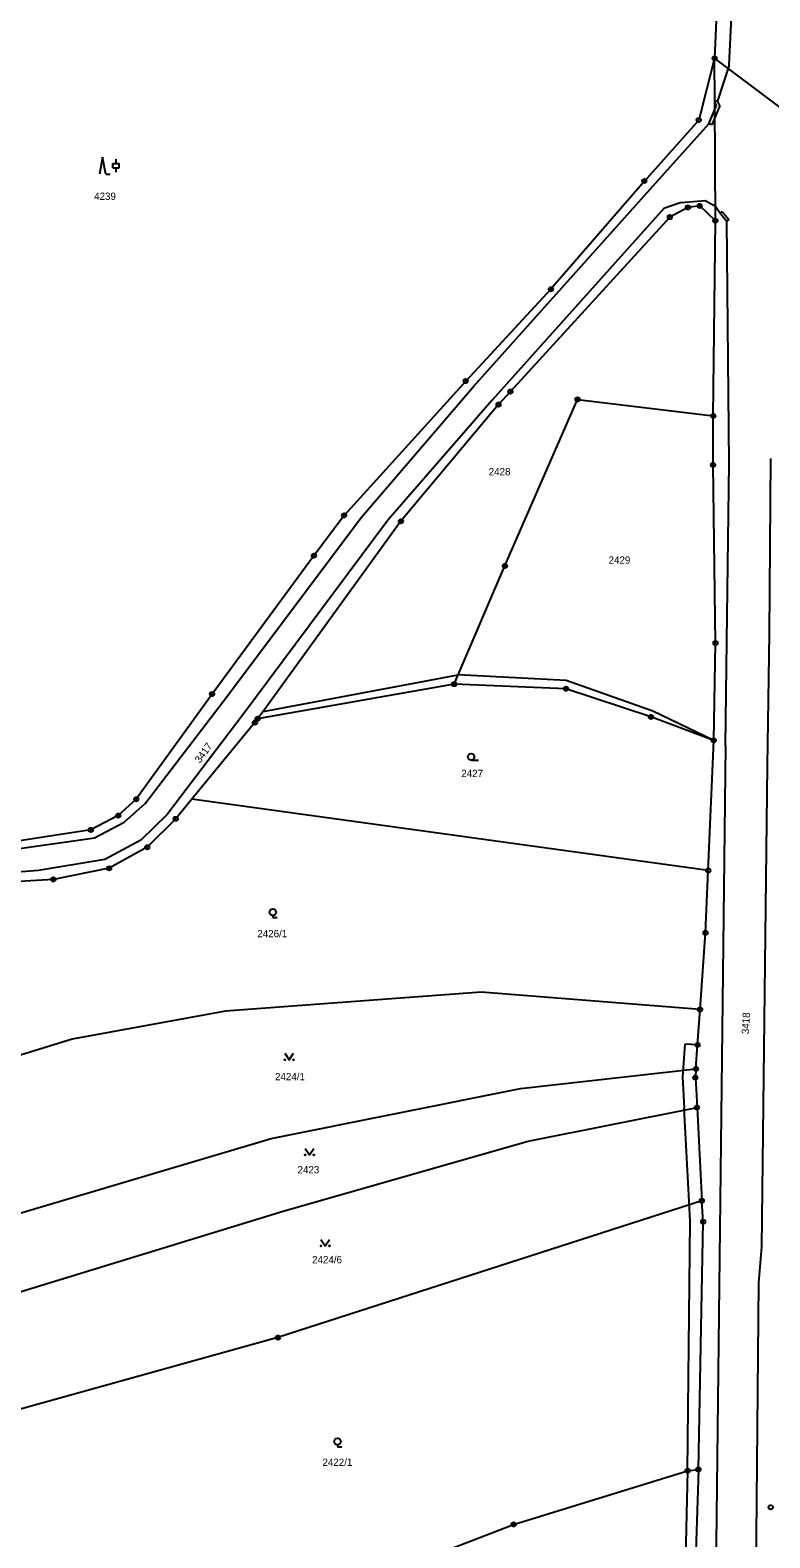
# Model space of a CAD drawing. Extents: x -733394 to -722299, y -1082822 to -1075049.
# Drawn here: x -729552.1 to -729380.2, y -1080085.2 to -1079734.5 of the extents above; entities that cross this region are included whole.
import ezdxf

# ---------------------------------------------------------------- set-up
doc = ezdxf.new("R2010")
doc.units = 0
for name, color, linetype in [('Hranice parcel', 7, 'Continuous'), ('Parcelní čísla', 7, 'Continuous'), ('Vnitřní kresba', 7, 'Continuous'), ('Značky bodu BP', 7, 'Continuous'), ('Značky kultur', 7, 'Continuous')]:
    doc.layers.add(name, color=color, linetype=linetype)

msp = doc.modelspace()

# ---------------------------------------------------------------- linework, layer by layer
at = {"layer": 'Hranice parcel'}
for p, q in [((-729375.36, -1079754.23), (-729393, -1079741.04)), ((-729393.31, -1079824.23), (-729392.83, -1079778.82)), ((-729453.54, -1079886.63), (-729499.23, -1079894.69)), ((-729394.5, -1079929.98), (-729393.2, -1079899.71)), ((-729394.5, -1079929.98), (-729514.52, -1079913.4)), ((-729397.1, -1079985.13), (-729395.98, -1080006.81)), ((-729399.29, -1080069.6), (-729400.21, -1080106.83))]:
    msp.add_line(p, q, dxfattribs=at)
for points in [[(-729389.9, -1079596.94), (-729389.91, -1079599.78), (-729391.17, -1079698.92), (-729393, -1079741.04)], [(-729393, -1079741.04), (-729396.69, -1079755.42), (-729409.34, -1079769.58), (-729431.05, -1079794.75), (-729450.87, -1079816.13), (-729479.14, -1079847.37), (-729486.14, -1079856.74), (-729509.81, -1079888.93), (-729527.42, -1079913.39), (-729531.62, -1079917.21), (-729537.99, -1079920.53), (-729560.17, -1079923.94), (-729604.91, -1079926.77), (-729628.92, -1079931.64), (-729650.34, -1079939.02)], [(-729392.83, -1079778.82), (-729392.95, -1079751.19), (-729393, -1079741.04)], [(-729392.83, -1079778.82), (-729396.48, -1079775.37), (-729399.23, -1079775.72), (-729403.42, -1079777.97), (-729440.47, -1079818.56), (-729443.24, -1079821.6), (-729465.91, -1079848.75), (-729497.97, -1079892.96), (-729499.23, -1079894.69)], [(-729453.54, -1079886.63), (-729452.59, -1079884.43), (-729441.74, -1079859.13), (-729424.88, -1079820.38), (-729393.31, -1079824.23)], [(-729393.2, -1079899.71), (-729392.8, -1079877.07), (-729393.37, -1079835.62), (-729393.31, -1079824.23)], [(-729393.2, -1079899.71), (-729407.8, -1079894.26), (-729427.58, -1079887.71), (-729453.54, -1079886.63)], [(-729499.23, -1079894.69), (-729499.86, -1079895.58), (-729514.52, -1079913.4)], [(-729514.52, -1079913.4), (-729518.27, -1079917.96), (-729524.89, -1079924.56), (-729533.73, -1079929.47), (-729546.69, -1079932.06), (-729554.56, -1079932.52)], [(-729396.38, -1079962.31), (-729395.13, -1079944.49), (-729394.5, -1079929.98)], [(-729396.38, -1079962.31), (-729447.28, -1079958.27), (-729506.69, -1079962.69), (-729542.32, -1079969.19), (-729585.71, -1079982.62)], [(-729397.35, -1079976.13), (-729396.96, -1079970.56), (-729396.38, -1079962.31)], [(-729572.38, -1080014.98), (-729571.76, -1080014.77), (-729496.1, -1079992.29), (-729438.14, -1079980.7), (-729397.35, -1079976.13)], [(-729397.35, -1079976.13), (-729397.49, -1079978.16), (-729397.1, -1079985.13)], [(-729565.64, -1080031.37), (-729493.03, -1080009.17), (-729436.31, -1079992.96), (-729397.1, -1079985.13)], [(-729395.98, -1080006.81), (-729494.49, -1080038.62), (-729562.8, -1080057.65)], [(-729399.29, -1080069.6), (-729396.78, -1080069.32), (-729395.67, -1080011.7), (-729395.98, -1080006.81)], [(-729539.17, -1080119.69), (-729518.46, -1080112.52), (-729439.72, -1080082.09), (-729399.29, -1080069.6)]]:
    msp.add_lwpolyline(points, dxfattribs=at)
at = {"layer": 'Vnitřní kresba'}
for p, q in [((-729389.59, -1079742.64), (-729387.65, -1079698.9)), ((-729389.59, -1079742.64), (-729392.31, -1079750.91)), ((-729394.32, -1079756.27), (-729392.58, -1079752.05)), ((-729391.8, -1079752), (-729393.67, -1079756.54)), ((-729392.31, -1079750.91), (-729392.95, -1079751.19)), ((-729392.58, -1079752.05), (-729392.95, -1079751.19)), ((-729391.8, -1079752), (-729392.31, -1079750.91)), ((-729408.02, -1079771.46), (-729394.32, -1079756.27)), ((-729393.67, -1079756.54), (-729394.32, -1079756.27)), ((-729449.08, -1079817.41), (-729408.02, -1079771.46)), ((-729400.8, -1079774.55), (-729404.85, -1079775.95)), ((-729400.8, -1079774.55), (-729395.2, -1079774.11)), ((-729395.2, -1079774.11), (-729392.83, -1079775.42)), ((-729404.85, -1079775.95), (-729444.69, -1079820.56)), ((-729392.83, -1079775.42), (-729391.71, -1079777.03)), ((-729391.71, -1079777.03), (-729391.28, -1079776.67)), ((-729391.71, -1079777.03), (-729390.13, -1079778.92)), ((-729391.28, -1079776.67), (-729389.7, -1079778.56)), ((-729389.7, -1079778.56), (-729390.13, -1079778.92)), ((-729389.64, -1079835.21), (-729390.13, -1079778.92)), ((-729475.05, -1079847.8), (-729449.08, -1079817.41)), ((-729444.69, -1079820.56), (-729468.86, -1079848.44)), ((-729380.24, -1079874.92), (-729379.95, -1079834.13)), ((-729390.13, -1079876.61), (-729389.64, -1079835.21)), ((-729507.22, -1079890.66), (-729475.05, -1079847.8)), ((-729468.86, -1079848.44), (-729502.63, -1079893.73)), ((-729390.46, -1079900.98), (-729390.13, -1079876.61)), ((-729380.7, -1079905.52), (-729380.24, -1079874.92)), ((-729497.97, -1079892.96), (-729452.59, -1079884.43)), ((-729427.5, -1079885.77), (-729452.59, -1079884.43)), ((-729407.35, -1079892.89), (-729427.5, -1079885.77)), ((-729525.36, -1079914.42), (-729507.22, -1079890.66)), ((-729502.63, -1079893.73), (-729520.23, -1079916.98)), ((-729393.2, -1079899.71), (-729407.35, -1079892.89)), ((-729390.46, -1079900.98), (-729391.76, -1080013.37)), ((-729382.05, -1080017.51), (-729380.7, -1079905.52)), ((-729530.22, -1079918.74), (-729525.36, -1079914.42)), ((-729537.12, -1079922.35), (-729530.22, -1079918.74)), ((-729520.23, -1079916.98), (-729526.37, -1079922.94)), ((-729557.85, -1079925.34), (-729537.12, -1079922.35)), ((-729526.37, -1079922.94), (-729534.72, -1079927.4)), ((-729534.72, -1079927.4), (-729550.12, -1079929.99)), ((-729550.12, -1079929.99), (-729597.35, -1079933.72)), ((-729399.95, -1079970.37), (-729400.48, -1079977.95)), ((-729396.96, -1079970.56), (-729399.95, -1079970.37)), ((-729400.48, -1079977.95), (-729400.1, -1079985.3)), ((-729398.94, -1080007), (-729400.1, -1079985.3)), ((-729398.67, -1080011.64), (-729398.94, -1080007)), ((-729399.29, -1080069.6), (-729398.67, -1080011.64)), ((-729391.76, -1080013.37), (-729393.66, -1080168.69)), ((-729382.71, -1080025.88), (-729382.05, -1080017.51)), ((-729384.02, -1080169.17), (-729382.71, -1080025.88)), ((-729396.78, -1080069.32), (-729397.91, -1080106.9))]:
    msp.add_line(p, q, dxfattribs=at)
at = {"layer": 'Značky bodu BP'}
for centre, radius in [((-729393, -1079741.04), 0.5), ((-729393, -1079741.04), 0.0303), ((-729396.69, -1079755.42), 0.5), ((-729396.69, -1079755.42), 0.0303), ((-729409.34, -1079769.58), 0.5), ((-729409.34, -1079769.58), 0.0303), ((-729396.48, -1079775.37), 0.5), ((-729403.42, -1079777.97), 0.5), ((-729403.42, -1079777.97), 0.0303), ((-729399.23, -1079775.72), 0.5), ((-729399.23, -1079775.72), 0.0303), ((-729396.48, -1079775.37), 0.0303), ((-729392.83, -1079778.82), 0.5), ((-729392.83, -1079778.82), 0.0303), ((-729431.05, -1079794.75), 0.5), ((-729431.05, -1079794.75), 0.0303), ((-729450.87, -1079816.13), 0.5), ((-729450.87, -1079816.13), 0.0303), ((-729440.47, -1079818.56), 0.5), ((-729440.47, -1079818.56), 0.0303), ((-729424.88, -1079820.38), 0.5), ((-729424.88, -1079820.38), 0.0303), ((-729443.24, -1079821.6), 0.5), ((-729443.24, -1079821.6), 0.0303), ((-729393.31, -1079824.23), 0.5), ((-729393.31, -1079824.23), 0.0303), ((-729393.37, -1079835.62), 0.5), ((-729393.37, -1079835.62), 0.0303), ((-729479.14, -1079847.37), 0.5), ((-729479.14, -1079847.37), 0.0303), ((-729465.91, -1079848.75), 0.5), ((-729465.91, -1079848.75), 0.0303), ((-729486.14, -1079856.74), 0.5), ((-729486.14, -1079856.74), 0.0303), ((-729441.74, -1079859.13), 0.5), ((-729441.74, -1079859.13), 0.0303), ((-729392.8, -1079877.07), 0.5), ((-729392.8, -1079877.07), 0.0303), ((-729453.54, -1079886.63), 0.5), ((-729453.54, -1079886.63), 0.0303), ((-729427.58, -1079887.71), 0.5), ((-729509.81, -1079888.93), 0.5), ((-729509.81, -1079888.93), 0.0303), ((-729427.58, -1079887.71), 0.0303), ((-729499.23, -1079894.69), 0.5), ((-729407.8, -1079894.26), 0.5), ((-729407.8, -1079894.26), 0.0303), ((-729499.86, -1079895.58), 0.5), ((-729499.86, -1079895.58), 0.0303), ((-729499.23, -1079894.69), 0.0303), ((-729393.2, -1079899.71), 0.5), ((-729393.2, -1079899.71), 0.0303), ((-729527.42, -1079913.39), 0.5), ((-729527.42, -1079913.39), 0.0303), ((-729531.62, -1079917.21), 0.5), ((-729531.62, -1079917.21), 0.0303), ((-729518.27, -1079917.96), 0.5), ((-729518.27, -1079917.96), 0.0303), ((-729537.99, -1079920.53), 0.5), ((-729537.99, -1079920.53), 0.0303), ((-729524.89, -1079924.56), 0.5), ((-729524.89, -1079924.56), 0.0303), ((-729533.73, -1079929.47), 0.5), ((-729546.69, -1079932.06), 0.5), ((-729546.69, -1079932.06), 0.0303), ((-729533.73, -1079929.47), 0.0303), ((-729394.5, -1079929.98), 0.5), ((-729394.5, -1079929.98), 0.0303), ((-729395.13, -1079944.49), 0.5), ((-729395.13, -1079944.49), 0.0303), ((-729396.38, -1079962.31), 0.5), ((-729396.38, -1079962.31), 0.0303), ((-729396.96, -1079970.56), 0.5), ((-729396.96, -1079970.56), 0.0303), ((-729397.49, -1079978.16), 0.5), ((-729397.35, -1079976.13), 0.5), ((-729397.49, -1079978.16), 0.0303), ((-729397.35, -1079976.13), 0.0303), ((-729397.1, -1079985.13), 0.5), ((-729397.1, -1079985.13), 0.0303), ((-729395.98, -1080006.81), 0.5), ((-729395.98, -1080006.81), 0.0303), ((-729395.67, -1080011.7), 0.5), ((-729395.67, -1080011.7), 0.0303), ((-729494.49, -1080038.62), 0.5), ((-729494.49, -1080038.62), 0.0303), ((-729399.29, -1080069.6), 0.5), ((-729399.29, -1080069.6), 0.0303), ((-729396.78, -1080069.32), 0.5), ((-729396.78, -1080069.32), 0.0303), ((-729379.96, -1080078.09), 0.5), ((-729439.72, -1080082.09), 0.5), ((-729439.72, -1080082.09), 0.0303)]:
    msp.add_circle(centre, radius, dxfattribs=at)
at = {"layer": 'Značky kultur'}
for p, q in [((-729535.25, -1079764.01), (-729536, -1079768.01)), ((-729534.5, -1079768.01), (-729535.25, -1079764.01)), ((-729534.5, -1079768.01), (-729533.5, -1079768.01)), ((-729532.87, -1079765.53), (-729531.37, -1079765.53)), ((-729532.87, -1079766.53), (-729532.87, -1079765.53)), ((-729532.87, -1079766.53), (-729531.37, -1079766.53)), ((-729532.12, -1079765.53), (-729532.12, -1079764.53)), ((-729532.12, -1079767.53), (-729532.12, -1079766.53)), ((-729531.37, -1079766.53), (-729531.37, -1079765.53)), ((-729449.61, -1079904.29), (-729447.86, -1079904.29)), ((-729495.68, -1079940.43), (-729495.68, -1079940.93)), ((-729495.68, -1079940.93), (-729494.68, -1079940.93)), ((-729480.67, -1080063.56), (-729480.67, -1080064.06)), ((-729480.67, -1080064.06), (-729479.67, -1080064.06))]:
    msp.add_line(p, q, dxfattribs=at)
for points in [[(-729492.87, -1079972.49), (-729491.87, -1079973.99), (-729490.87, -1079972.49)], [(-729488.19, -1079994.64), (-729487.19, -1079996.14), (-729486.19, -1079994.64)], [(-729484.5, -1080015.81), (-729483.5, -1080017.31), (-729482.5, -1080015.81)]]:
    msp.add_lwpolyline(points, dxfattribs=at)
for centre, radius in [((-729449.61, -1079903.54), 0.75), ((-729495.68, -1079939.68), 0.75), ((-729492.87, -1079973.99), 0.1), ((-729490.87, -1079973.99), 0.1), ((-729488.19, -1079996.14), 0.1), ((-729486.19, -1079996.14), 0.1), ((-729484.5, -1080017.31), 0.1), ((-729482.5, -1080017.31), 0.1), ((-729480.67, -1080062.81), 0.75)]:
    msp.add_circle(centre, radius, dxfattribs=at)

# ---------------------------------------------------------------- texts
at = {"layer": 'Parcelní čísla'}
for s, p in [('4239', (-729537.22, -1079773.97)), ('2428', (-729445.52, -1079838.05)), ('2429', (-729417.66, -1079858.61)), ('2427', (-729451.89, -1079908.25)), ('2426/1', (-729499.3, -1079945.51)), ('2424/1', (-729495.18, -1079978.78)), ('2423', (-729489.95, -1080000.44)), ('2424/6', (-729486.57, -1080021.36)), ('2422/1', (-729484.16, -1080068.49))]:
    msp.add_text(s, height=1.7, dxfattribs=at).set_placement(p)
for s, rotation, p in [('3417', 54, (-729512.62, -1079905.15)), ('3418', 87, (-729385.04, -1079968.09))]:
    msp.add_text(s, height=1.7, rotation=rotation, dxfattribs=at).set_placement(p)

doc.saveas('drawing.dxf')
